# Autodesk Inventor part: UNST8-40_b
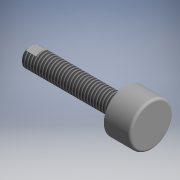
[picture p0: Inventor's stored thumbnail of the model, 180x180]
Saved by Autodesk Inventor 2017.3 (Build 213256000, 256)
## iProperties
Part Number: UNST8-40_b
Material: Generic
Catalog Web Link: www.cadenas.de
Description: UNST_b-Shock Absorption Stoppers -Screws with Low Elastic Rubber-
Vendor: MISUMI
Document SubType Name: Modeling
Designer: partserver
Manufacturer: MISUMI
Mass: 4.76948 g
Surface Area: 20.9944 cm^2
Volume: 4.76948 cm^3
Density: 1 g/cm^3
Appearance: PSOLRGB-192-192-192
Category: PARTsolutions
Company: MISUMI
Title: UNST8-40_b
Author: Cadenas PARTsolutions
Comments: Shock Absorption Stoppers -Screws with Low Elastic Rubber-
PSOL_IDENT_0: {$CADENAS_DATA\23d-libs\misumi\metric\15_locating_components\unst_b.prj},162 {VTYP=3D},{NB=UNST8-40_
PSOL_IDENT_1: b},{LINA=UNST8-40_b},{NN=UNST_b},{DATE=02.06.2021 05:59:50},{GEOMDATE=21.02.2011 00:00:00},{VERSION=
PSOL_IDENT_2: },{LINEID=50},{WBVAR=L},{WBNUMERIC=L}  {NB=UNST8-40_b},{LINA=UNST8-40_b},{KT=DUMMY},{PN=UNST8-40},{T
PSOL_IDENT_3: YPE=UNST},{MAT=304 Stainless Steel},{MATS=Low Elastic Rubber},{HARDS=Shore A57},{AC=304 Stainless St
PSOL_IDENT_4: eel},{M=8},{MMIN=6.647},{L=40},{L1=30,'30',40,'40',50,'50'},{TT=5.7},{C=18},{D=14.40},{B=13.0},{H=11
PSOL_IDENT_5: },{E=5.3},{MM=5.0},{W=6.5},{IT=0.676}
NB: UNST8-40_b
NN: UNST_b
NT: Shock Absorption Stoppers -Screws with Low Elastic Rubber-
NBSYN: $PN._b
LINA: UNST8-40_b
CATALOG: Misumi
PN: UNST8-40
M: 8
L: 40
TT: 5.7
C: 18
D: 14.4
B: 13
H: 11
E: 5.3
MM: 5
W: 6.5
SUPPLIER: MISUMI
ARTICLENO: UNST8-40_b
BOMINFO: UNST8-40_b
CREATOR: CADENAS GmbH
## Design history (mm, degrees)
sketch "Sketch_1"
  geometry: L1 (40, 0)-(-11, 0); L2 (-11, 0)-(-11, 8); L3 (-10, 9)-(0, 9); L4 (0, 9)-(0, 4); L5 (0, 4)-(39.233, 4); L6 (39.233, 4)-(40, 3.233); L7 (40, 3.233)-(40, 0); L8 (40, 0)-(-11, 0); A1 r 1 centre (-10, 8) between (-10, 9) and (-11, 8)
  constraints: 16 end point, 2 point on circle, 1 centre point
revolve "Revolution1" sketch "Sketch_1" stored, may be unused: angle "d0" = 360 deg
thread "Thread1" dims "d1" = 39.233, "d2" = 0
sketch "Sketch_4"
  geometry: L1 (-18, 18)-(-18, -18); L2 (-18, -18)-(18, -18); L3 (18, -18)-(18, 18); L4 (18, 18)-(-18, 18); L5 (-3.25, 6.5)-(-3.25, -6.5); L6 (-3.25, -6.5)-(3.25, -6.5); L7 (3.25, -6.5)-(3.25, 6.5); L8 (3.25, 6.5)-(-3.25, 6.5)
  constraints: 16 end point
extrude "Extrusion1" cut sketch "Sketch_4" distance "d3" = 5; taper "d4" = 0 deg
node "unstb_n_XY"
node "unstb_n_YZ"
node "unstb_n_ZX"
node "unstb_n_X"
node "unstb_n_Y"
node "unstb_n_Z"
node "unstb_n_Center"
body "Solid1"
